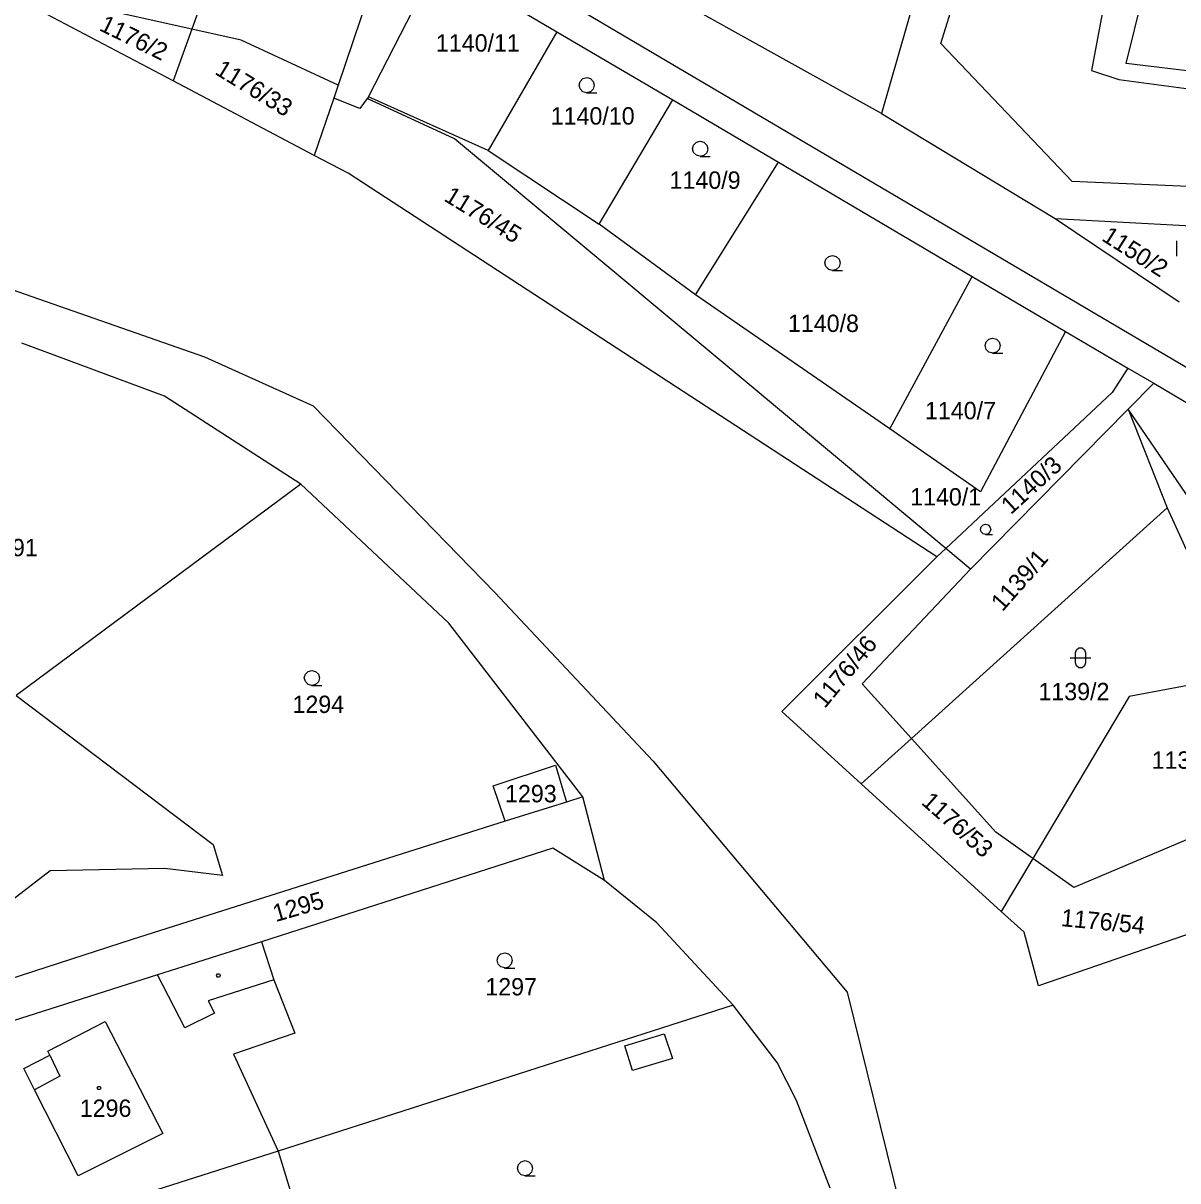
# Model space of a CAD drawing. Extents: x -621797 to -620972, y -1175539 to -1174697.
# Drawn here: x -621620.7 to -621507.6, y -1175244 to -1175130.5 of the extents above; entities that cross this region are included whole.
import ezdxf

# ---------------------------------------------------------------- set-up
doc = ezdxf.new("R2010")
doc.units = 0
for name, color, linetype in [('Rozvod plynu EON', 7, 'Continuous'), ('SDEL EON', 7, 'Continuous'), ('SDEL EON - popis', 7, 'Continuous'), ('Silnoproud EON', 7, 'Continuous'), ('Silnoproud EON - popis', 7, 'Continuous')]:
    doc.layers.add(name, color=color, linetype=linetype)

msp = doc.modelspace()

# ---------------------------------------------------------------- linework, layer by layer
at = {"layer": 'Rozvod plynu EON'}
for points in [[(-621601.48, -1175223.7), (-621601.39, -1175223.85), (-621601.48, -1175224), (-621601.66, -1175224), (-621601.75, -1175223.85), (-621601.66, -1175223.7)], [(-621613.16, -1175234.73), (-621613.07, -1175234.88), (-621613.16, -1175235.03), (-621613.34, -1175235.03), (-621613.43, -1175234.88), (-621613.34, -1175234.73)]]:
    msp.add_lwpolyline(points, close=True, dxfattribs=at)
at = {"layer": 'SDEL EON'}
msp.add_line((-621507.75, -1175151.87), (-621507.75, -1175153.37), dxfattribs=at)
for points in [[(-621565.5, -1175137.36), (-621565.88, -1175137.26), (-621566.15, -1175136.99), (-621566.25, -1175136.62), (-621566.15, -1175136.25), (-621565.88, -1175135.98), (-621565.51, -1175135.88), (-621565.14, -1175135.98), (-621564.87, -1175136.25), (-621564.77, -1175136.63), (-621564.87, -1175137.01), (-621565.14, -1175137.28), (-621565.52, -1175137.38), (-621564.52, -1175137.38)], [(-621554.39, -1175143.59), (-621554.77, -1175143.49), (-621555.04, -1175143.22), (-621555.14, -1175142.85), (-621555.04, -1175142.48), (-621554.77, -1175142.21), (-621554.4, -1175142.11), (-621554.03, -1175142.21), (-621553.76, -1175142.48), (-621553.66, -1175142.86), (-621553.76, -1175143.24), (-621554.03, -1175143.51), (-621554.41, -1175143.61), (-621553.41, -1175143.61)], [(-621541.43, -1175154.77), (-621541.81, -1175154.67), (-621542.08, -1175154.4), (-621542.18, -1175154.03), (-621542.08, -1175153.66), (-621541.81, -1175153.39), (-621541.44, -1175153.29), (-621541.07, -1175153.39), (-621540.8, -1175153.66), (-621540.7, -1175154.04), (-621540.8, -1175154.42), (-621541.07, -1175154.69), (-621541.45, -1175154.79), (-621540.45, -1175154.79)], [(-621525.75, -1175162.87), (-621526.13, -1175162.77), (-621526.4, -1175162.5), (-621526.5, -1175162.13), (-621526.4, -1175161.76), (-621526.13, -1175161.49), (-621525.76, -1175161.39), (-621525.39, -1175161.49), (-621525.12, -1175161.76), (-621525.02, -1175162.14), (-621525.12, -1175162.52), (-621525.39, -1175162.79), (-621525.77, -1175162.89), (-621524.77, -1175162.89)], [(-621526.44, -1175180.63), (-621526.695, -1175180.563), (-621526.876, -1175180.382), (-621526.942, -1175180.134), (-621526.876, -1175179.886), (-621526.695, -1175179.705), (-621526.447, -1175179.638), (-621526.199, -1175179.705), (-621526.018, -1175179.886), (-621525.951, -1175180.141), (-621526.018, -1175180.395), (-621526.199, -1175180.576), (-621526.453, -1175180.643), (-621525.783, -1175180.643)], [(-621518.16, -1175192.73), (-621516.89, -1175192.73), (-621516.16, -1175192.73)], [(-621592.41, -1175195.43), (-621592.79, -1175195.33), (-621593.06, -1175195.06), (-621593.16, -1175194.69), (-621593.06, -1175194.32), (-621592.79, -1175194.05), (-621592.42, -1175193.95), (-621592.05, -1175194.05), (-621591.78, -1175194.32), (-621591.68, -1175194.7), (-621591.78, -1175195.08), (-621592.05, -1175195.35), (-621592.43, -1175195.45), (-621591.43, -1175195.45)], [(-621573.53, -1175223.1), (-621573.91, -1175223), (-621574.18, -1175222.73), (-621574.28, -1175222.36), (-621574.18, -1175221.99), (-621573.91, -1175221.72), (-621573.54, -1175221.62), (-621573.17, -1175221.72), (-621572.9, -1175221.99), (-621572.8, -1175222.37), (-621572.9, -1175222.75), (-621573.17, -1175223.02), (-621573.55, -1175223.12), (-621572.55, -1175223.12)], [(-621571.54, -1175243.47), (-621571.92, -1175243.37), (-621572.19, -1175243.1), (-621572.29, -1175242.73), (-621572.19, -1175242.36), (-621571.92, -1175242.09), (-621571.55, -1175241.99), (-621571.18, -1175242.09), (-621570.91, -1175242.36), (-621570.81, -1175242.74), (-621570.91, -1175243.12), (-621571.18, -1175243.39), (-621571.56, -1175243.49), (-621570.56, -1175243.49)]]:
    msp.add_lwpolyline(points, dxfattribs=at)
msp.add_lwpolyline([(-621517.66, -1175192.23), (-621517.56, -1175191.94), (-621517.31, -1175191.76), (-621517, -1175191.76), (-621516.75, -1175191.94), (-621516.65, -1175192.23), (-621516.65, -1175193.23), (-621516.75, -1175193.52), (-621517, -1175193.7), (-621517.31, -1175193.7), (-621517.56, -1175193.52), (-621517.66, -1175193.23)], close=True, dxfattribs=at)
at = {"layer": 'SDEL EON - popis'}
for p, q in [((-621530.82, -1175132.54), (-621523.08, -1175107.22)), ((-621511.39, -1175109.68), (-621516.07, -1175135.19)), ((-621517.96, -1175146.05), (-621530.82, -1175132.54)), ((-621516.07, -1175135.19), (-621513.39, -1175136.05)), ((-621513.39, -1175136.05), (-621486.76, -1175139.69)), ((-621498.76, -1175146.88), (-621517.96, -1175146.05)), ((-621604.85, -1175228.98), (-621607.52, -1175223.78)), ((-621596.14, -1175224.28), (-621602.57, -1175226.34)), ((-621602.57, -1175226.34), (-621601.94, -1175227.55)), ((-621601.94, -1175227.55), (-621604.85, -1175228.98)), ((-621618.29, -1175231.26), (-621612.66, -1175228.34)), ((-621612.66, -1175228.34), (-621607.02, -1175239.34)), ((-621561.77, -1175230.74), (-621557.91, -1175229.56)), ((-621557.91, -1175229.56), (-621557.12, -1175231.98)), ((-621561.03, -1175233.17), (-621561.77, -1175230.74)), ((-621620.62, -1175232.97), (-621618.09, -1175231.67)), ((-621618.09, -1175231.67), (-621618.29, -1175231.26)), ((-621618.09, -1175231.67), (-621617.11, -1175233.72)), ((-621557.12, -1175231.98), (-621561.03, -1175233.17)), ((-621619.57, -1175235.06), (-621620.62, -1175232.97)), ((-621617.11, -1175233.72), (-621619.57, -1175235.06)), ((-621615.32, -1175243.48), (-621619.57, -1175235.06)), ((-621607.02, -1175239.34), (-621615.32, -1175243.48))]:
    msp.add_line(p, q, dxfattribs=at)
at = {"layer": 'Silnoproud EON'}
for p, q in [((-621512.68, -1175134.5), (-621504.52, -1175101.59)), ((-621527.86, -1175108.67), (-621536.65, -1175139.4)), ((-621583.73, -1175118.84), (-621484.26, -1175177.55)), ((-621600.87, -1175121.97), (-621604.18, -1175131.13)), ((-621584.8, -1175121.74), (-621589.84, -1175136.61)), ((-621586.88, -1175137.77), (-621580.09, -1175124.51)), ((-621580.09, -1175124.51), (-621568.43, -1175131.39)), ((-621536.65, -1175139.4), (-621559.97, -1175126.4)), ((-621604.18, -1175131.13), (-621620.04, -1175127.59)), ((-621606.01, -1175136.2), (-621620.28, -1175128.67)), ((-621604.18, -1175131.13), (-621606.01, -1175136.2)), ((-621599.35, -1175132.21), (-621604.18, -1175131.13)), ((-621589.84, -1175136.61), (-621599.35, -1175132.21)), ((-621568.43, -1175131.39), (-621575.17, -1175143.02)), ((-621568.43, -1175131.39), (-621557.09, -1175138.07)), ((-621483.82, -1175137.93), (-621512.68, -1175134.5)), ((-621592.18, -1175143.51), (-621606.01, -1175136.2)), ((-621589.84, -1175136.61), (-621590.27, -1175137.89)), ((-621590.27, -1175137.89), (-621592.18, -1175143.51)), ((-621587.71, -1175138.89), (-621590.27, -1175137.89)), ((-621587, -1175137.93), (-621587.71, -1175138.89)), ((-621586.88, -1175137.77), (-621587, -1175137.93)), ((-621578.44, -1175141.88), (-621587, -1175137.93)), ((-621575.17, -1175143.02), (-621586.88, -1175137.77)), ((-621564.3, -1175150.25), (-621557.09, -1175138.07)), ((-621557.09, -1175138.07), (-621546.74, -1175144.17)), ((-621536.65, -1175139.4), (-621519.63, -1175149.69)), ((-621530.35, -1175182), (-621578.44, -1175141.88)), ((-621588.88, -1175145.25), (-621592.18, -1175143.51)), ((-621575.17, -1175143.02), (-621564.3, -1175150.25)), ((-621554.86, -1175157.15), (-621546.74, -1175144.17)), ((-621546.74, -1175144.17), (-621527.75, -1175155.36)), ((-621531.24, -1175182.84), (-621588.88, -1175145.25)), ((-621649.41, -1175147.01), (-621602.94, -1175163.25)), ((-621554.86, -1175157.15), (-621564.3, -1175150.25)), ((-621519.63, -1175149.69), (-621507.5, -1175157.84)), ((-621519.63, -1175149.69), (-621504.77, -1175150.48)), ((-621535.82, -1175170.3), (-621527.75, -1175155.36)), ((-621527.75, -1175155.36), (-621518.61, -1175160.74)), ((-621535.82, -1175170.3), (-621554.86, -1175157.15)), ((-621518.61, -1175160.74), (-621526.94, -1175176.45)), ((-621518.61, -1175160.74), (-621512.51, -1175164.34)), ((-621606.85, -1175167.08), (-621620.81, -1175161.91)), ((-621602.94, -1175163.25), (-621592.28, -1175168.04)), ((-621512.51, -1175164.34), (-621514.04, -1175166.74)), ((-621512.51, -1175164.34), (-621509.98, -1175165.83)), ((-621512.49, -1175168.37), (-621509.98, -1175165.83)), ((-621509.98, -1175165.83), (-621486.07, -1175179.93)), ((-621593.5, -1175175.72), (-621606.85, -1175167.08)), ((-621514.04, -1175166.74), (-621530.35, -1175182)), ((-621592.28, -1175168.04), (-621574.49, -1175186.32)), ((-621527.92, -1175184.03), (-621512.49, -1175168.37)), ((-621512.49, -1175168.37), (-621508.68, -1175178.04)), ((-621502.15, -1175183.5), (-621512.49, -1175168.37)), ((-621526.94, -1175176.45), (-621535.82, -1175170.3)), ((-621593.5, -1175175.72), (-621621.38, -1175196.43)), ((-621579.01, -1175189.32), (-621593.5, -1175175.72)), ((-621508.68, -1175178.04), (-621533.7, -1175200.63)), ((-621508.68, -1175178.04), (-621501.21, -1175194.41)), ((-621530.35, -1175182), (-621531.24, -1175182.84)), ((-621527.92, -1175184.03), (-621530.35, -1175182)), ((-621546.4, -1175197.98), (-621531.24, -1175182.84)), ((-621538.52, -1175195.28), (-621527.92, -1175184.03)), ((-621574.49, -1175186.32), (-621558.99, -1175202.84)), ((-621565.89, -1175206.35), (-621579.01, -1175189.32)), ((-621501.21, -1175194.41), (-621512.39, -1175196.52)), ((-621533.7, -1175200.63), (-621538.52, -1175195.28)), ((-621621.38, -1175196.43), (-621602.09, -1175211.03)), ((-621512.39, -1175196.52), (-621521.83, -1175212.38)), ((-621538.62, -1175205.07), (-621546.4, -1175197.98)), ((-621533.7, -1175200.63), (-621538.62, -1175205.07)), ((-621525.46, -1175209.79), (-621533.7, -1175200.63)), ((-621558.99, -1175202.84), (-621540, -1175225.47)), ((-621574.67, -1175205.25), (-621568.58, -1175203.23)), ((-621568.58, -1175203.23), (-621567.5, -1175206.85)), ((-621524.91, -1175217.57), (-621538.62, -1175205.07)), ((-621573.48, -1175208.72), (-621574.67, -1175205.25)), ((-621567.5, -1175206.85), (-621573.48, -1175208.72)), ((-621565.89, -1175206.35), (-621567.5, -1175206.85)), ((-621563.77, -1175214.55), (-621565.89, -1175206.35)), ((-621498.74, -1175207.15), (-621517.81, -1175215.24)), ((-621573.48, -1175208.72), (-621610.03, -1175220.32)), ((-621521.83, -1175212.38), (-621525.46, -1175209.79)), ((-621602.09, -1175211.03), (-621601.17, -1175214.06)), ((-621568.84, -1175211.36), (-621597.34, -1175220.54)), ((-621563.77, -1175214.55), (-621568.84, -1175211.36)), ((-621521.83, -1175212.38), (-621524.91, -1175217.57)), ((-621517.81, -1175215.24), (-621521.83, -1175212.38)), ((-621618.03, -1175213.59), (-621631.96, -1175224.3)), ((-621606.83, -1175213.37), (-621618.03, -1175213.59)), ((-621601.17, -1175214.06), (-621606.83, -1175213.37)), ((-621558.63, -1175218.68), (-621563.77, -1175214.55)), ((-621522.68, -1175219.6), (-621524.91, -1175217.57)), ((-621551.18, -1175226.75), (-621558.63, -1175218.68)), ((-621500.3, -1175217.61), (-621521.27, -1175224.85)), ((-621521.27, -1175224.85), (-621522.68, -1175219.6)), ((-621610.03, -1175220.32), (-621629.91, -1175226.79)), ((-621597.34, -1175220.54), (-621604.42, -1175222.79)), ((-621597.34, -1175220.54), (-621596.14, -1175224.28)), ((-621604.42, -1175222.79), (-621607.52, -1175223.78)), ((-621607.52, -1175223.78), (-621628.06, -1175230.33)), ((-621596.14, -1175224.28), (-621594.1, -1175229.51)), ((-621540, -1175225.47), (-621532.1, -1175257.48)), ((-621551.18, -1175226.75), (-621595.72, -1175241.05)), ((-621546.87, -1175232.38), (-621551.18, -1175226.75)), ((-621594.1, -1175229.51), (-621600.1, -1175231.57)), ((-621600.1, -1175231.57), (-621595.72, -1175241.05)), ((-621544.96, -1175236.09), (-621546.87, -1175232.38)), ((-621541.66, -1175244.7), (-621544.96, -1175236.09)), ((-621595.72, -1175241.05), (-621618.87, -1175248.42)), ((-621595.72, -1175241.05), (-621590.94, -1175256.75))]:
    msp.add_line(p, q, dxfattribs=at)

# ---------------------------------------------------------------- texts
at = {"layer": 'Silnoproud EON - popis'}
for s, rotation, p in [('1176/2', 333.9198, (-621613.337, -1175131.203)), ('1176/33', 328.4767, (-621602.015, -1175135.475)), ('1176/45', 328.4767, (-621579.585, -1175147.885)), ('1150/2', 327.61727, (-621515.178, -1175151.78)), ('1140/3', 42.28429, (-621523.979, -1175178.756)), ('1139/1', 48.58682, (-621524.8, -1175188.265)), ('1176/46', 50.42029, (-621542.2, -1175197.757)), ('1176/53', 318.62183, (-621532.835, -1175206.99)), ('1295', 16.21471, (-621595.953, -1175218.62)), ('1176/54', 354.60358, (-621519.119, -1175219.007))]:
    msp.add_text(s, height=1.7, rotation=rotation, dxfattribs=at).set_placement(p)
for s, p in [('1140/11', (-621580.276, -1175133.33)), ('1140/10', (-621569.031, -1175140.48)), ('1140/9', (-621557.393, -1175146.77)), ('1140/8', (-621545.803, -1175160.8)), ('1140/7', (-621532.383, -1175169.35)), ('1140/1', (-621533.837, -1175177.8)), ('1291', (-621624.317, -1175182.77)), ('1139/2', (-621521.277, -1175196.88)), ('1294', (-621594.317, -1175198.13)), ('1139/3', (-621510.187, -1175203.59)), ('1293', (-621573.506, -1175206.88)), ('1297', (-621575.437, -1175225.8)), ('1296', (-621615.147, -1175237.7))]:
    msp.add_text(s, height=1.7, dxfattribs=at).set_placement(p)

doc.saveas('drawing.dxf')
